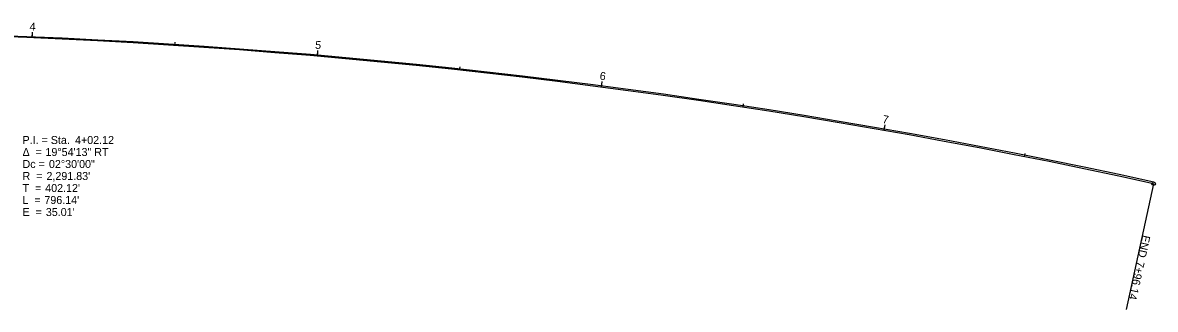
# Model space of a CAD drawing. Extents: x 2196792 to 2197586, y 661568 to 661670.
# Drawn here: x 2197189.4 to 2197585.7, y 661567.7 to 661668 of the extents above; entities that cross this region are included whole.
import ezdxf

# ---------------------------------------------------------------- set-up
doc = ezdxf.new("R2010")
doc.units = 0
for name, color, linetype in [('Default', 7, 'Continuous'), ('GE_X_Alignment', 7, 'Continuous'), ('GE_X_Alignment_1000_Stations', 7, 'Continuous'), ('GE_X_Alignment_100_Curve_Data', 7, 'Continuous'), ('GE_X_Alignment_100_Stations', 7, 'Continuous'), ('GE_X_Alignment_500_Curve_Data', 7, 'Continuous'), ('GE_X_Alignment_500_Stations', 7, 'Continuous'), ('SC_Scratch2', 7, 'Continuous')]:
    doc.layers.add(name, color=color, linetype=linetype)

msp = doc.modelspace()

# ---------------------------------------------------------------- linework, layer by layer
at = {"layer": 'Default'}
for centre in [(2197192.74, 661662.76), (2197292.52, 661656.28), (2197292.52, 661656.28), (2197391.92, 661645.46), (2197490.76, 661630.32), (2197585.08, 661611.71), (2197585.08, 661611.71), (2197585.08, 661611.71)]:
    msp.add_circle(centre, 0.0000833, dxfattribs=at)
at = {"layer": 'GE_X_Alignment'}
msp.add_arc((2197094.29, 659373.04), 2291.83, 77.6346, 97.53811, dxfattribs=at)
at = {"layer": 'GE_X_Alignment_1000_Stations'}
for p, q in [((2197292.52, 661656.28), (2197292.62, 661657.48)), ((2197585.08, 661611.71), (2197575.44, 661567.75))]:
    msp.add_line(p, q, dxfattribs=at)
msp.add_circle((2197585.08, 661611.71), 0.6, dxfattribs=at)
at = {"layer": 'GE_X_Alignment_100_Stations'}
for p, q in [((2197192.74, 661662.76), (2197192.82, 661664.75)), ((2197242.66, 661660.06), (2197242.74, 661661.26)), ((2197292.52, 661656.28), (2197292.69, 661658.28)), ((2197342.28, 661651.42), (2197342.41, 661652.61)), ((2197391.92, 661645.46), (2197392.18, 661647.45)), ((2197441.43, 661638.43), (2197441.61, 661639.62)), ((2197490.76, 661630.32), (2197491.11, 661632.29)), ((2197539.91, 661621.13), (2197540.14, 661622.31)), ((2197585.08, 661611.71), (2197575.44, 661567.75))]:
    msp.add_line(p, q, dxfattribs=at)
msp.add_circle((2197585.08, 661611.71), 0.6, dxfattribs=at)
at = {"layer": 'GE_X_Alignment_500_Stations'}
for p, q in [((2197192.74, 661662.76), (2197192.79, 661663.96)), ((2197292.52, 661656.28), (2197292.69, 661658.28)), ((2197391.92, 661645.46), (2197392.08, 661646.65)), ((2197490.76, 661630.32), (2197490.97, 661631.5)), ((2197585.08, 661611.71), (2197575.44, 661567.75))]:
    msp.add_line(p, q, dxfattribs=at)
msp.add_circle((2197585.08, 661611.71), 0.6, dxfattribs=at)
at = {"layer": 'SC_Scratch2'}
msp.add_arc((2197095.93, 659373.26), 2291.83, 77.6734, 97.57937, dxfattribs=at)

# ---------------------------------------------------------------- texts
at = {"layer": 'GE_X_Alignment_1000_Stations'}
for s, p in [('END', (2197581.22, 661593.89)), ('7+96.14', (2197579.22, 661584.76))]:
    msp.add_text(s, height=2.8, rotation=257.6346, dxfattribs=at).set_placement(p)
at = {"layer": 'GE_X_Alignment_100_Curve_Data'}
for s, p in [('P.I. = Sta. ', (2197189.36, 661625.59)), ('4+02.12', (2197207.73, 661625.59)), ('Δ  = ', (2197189.36, 661621.39)), ('19°54\'13" RT', (2197197.38, 661621.39)), ('Dc = ', (2197189.36, 661617.19)), ('02°30\'00"', (2197198.6, 661617.19)), ('R  = ', (2197189.36, 661612.99)), ("2,291.83'", (2197197.73, 661612.99)), ('T  = ', (2197189.36, 661608.79)), ("402.12'", (2197197.29, 661608.79)), ('L  = ', (2197189.36, 661604.59)), ("796.14'", (2197197, 661604.59)), ('E  = ', (2197189.36, 661600.39)), ("35.01'", (2197197.51, 661600.39))]:
    msp.add_text(s, height=2.8, dxfattribs=at).set_placement(p)
at = {"layer": 'GE_X_Alignment_100_Stations'}
for s, rotation, p in [('4', 357.5381, (2197191.78, 661665.3)), ('5', 355.0381, (2197291.63, 661658.92)), ('6', 352.5381, (2197391.16, 661648.13)), ('7', 350.0381, (2197490.05, 661632.98)), ('END', 257.6346, (2197581.22, 661593.89)), ('7+96.14', 257.6346, (2197579.22, 661584.76))]:
    msp.add_text(s, height=2.8, rotation=rotation, dxfattribs=at).set_placement(p)
at = {"layer": 'GE_X_Alignment_500_Curve_Data'}
for s, p in [('P.I. = Sta. ', (2197189.36, 661625.59)), ('4+02.12', (2197207.73, 661625.59)), ('Δ  = ', (2197189.36, 661621.39)), ('19°54\'13" RT', (2197197.38, 661621.39)), ('Dc = ', (2197189.36, 661617.19)), ('02°30\'00"', (2197198.6, 661617.19)), ('R  = ', (2197189.36, 661612.99)), ("2,291.83'", (2197197.73, 661612.99)), ('T  = ', (2197189.36, 661608.79)), ("402.12'", (2197197.29, 661608.79)), ('L  = ', (2197189.36, 661604.59)), ("796.14'", (2197197, 661604.59)), ('E  = ', (2197189.36, 661600.39)), ("35.01'", (2197197.51, 661600.39))]:
    msp.add_text(s, height=2.8, dxfattribs=at).set_placement(p)
at = {"layer": 'GE_X_Alignment_500_Stations'}
for s, rotation, p in [('5', 355.0381, (2197291.63, 661658.92)), ('END', 257.6346, (2197581.22, 661593.89)), ('7+96.14', 257.6346, (2197579.22, 661584.76))]:
    msp.add_text(s, height=2.8, rotation=rotation, dxfattribs=at).set_placement(p)

doc.saveas('drawing.dxf')
